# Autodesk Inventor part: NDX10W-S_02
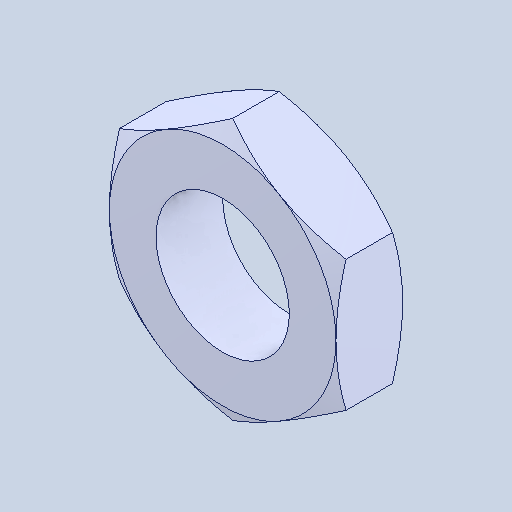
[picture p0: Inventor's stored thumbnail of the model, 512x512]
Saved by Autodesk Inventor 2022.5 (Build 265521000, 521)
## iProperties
Created: 2024-05
Part Number: NDX10W-S_02
Material: 一般
Document SubType Name: Modeling
Designer: ImaoCorp
Density: 1 g/cm^3
Appearance: 既定
Author: ImaoCorp
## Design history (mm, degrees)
feature "NDX10W-S_02"
node "ソリッド1"
